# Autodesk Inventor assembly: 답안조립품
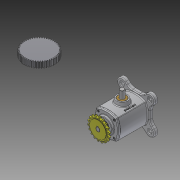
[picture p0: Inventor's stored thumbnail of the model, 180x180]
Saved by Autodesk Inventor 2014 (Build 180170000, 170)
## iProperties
Created: 2016-05
Part Number: 답안조립품
Document SubType Name: Assembly
Designer: J.H.Beak
Author: J.H.Beak
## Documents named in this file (12)
- C:\Users\Administrator\Desktop\460507V1026\답안조립품.iam
- C:\Users\Administrator\Desktop\460507V1026\본체.ipt
- C:\Users\Administrator\Desktop\460507V1026\M4x0.7x12.ipt
- C:\Users\Administrator\Desktop\460507V1026\베어링-6203.ipt
- C:\Users\Administrator\Desktop\460507V1026\부시.ipt
- C:\Users\Administrator\Desktop\460507V1026\스퍼기어.ipt
- C:\Users\Administrator\Desktop\460507V1026\스프로킷.ipt
- C:\Users\Administrator\Desktop\460507V1026\슬라이더.ipt
- C:\Users\Administrator\Desktop\460507V1026\오일실.ipt
- C:\Users\Administrator\Desktop\460507V1026\커버.ipt
- C:\Users\Administrator\Desktop\460507V1026\키5x5.ipt
- C:\Users\Administrator\Desktop\460507V1026\편심축.ipt
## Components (8 placed, 1 different names)
1. M4x0.7x12:2
2. M4x0.7x12:3
3. M4x0.7x12:4
4. M4x0.7x12:5
5. M4x0.7x12:1
6. M4x0.7x12:6
7. M4x0.7x12:7
8. M4x0.7x12:8
